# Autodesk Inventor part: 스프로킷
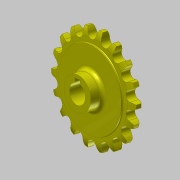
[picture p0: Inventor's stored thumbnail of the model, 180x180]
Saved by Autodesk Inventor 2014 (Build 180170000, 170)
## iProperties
Created: 2016-03
Part Number: 스프로킷
Material: 강철, 탄소
Document SubType Name: Modeling
Designer: mduedu
Density: 7.87 g/cm^3
Mass: 301.818 g
Surface Area: 124.882 cm^2
Volume: 38.3505 cm^3
Appearance: 매끄러움 - 노란색
Author: mduedu
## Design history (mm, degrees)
sketch "스케치1"
  geometry: L1 (0, 5)-(29.5, 5); L2 (29.5, 5)-(29.5, 4.1); L3 (30, 3.6)-(33.625, 3.6); L4 (40, 2)-(40, 0); L5 (40, 0)-(0, 0); L6 (0, 0)-(0, 5); L7 (0, -5)-(29.5, -5); L8 (29.5, -5)-(29.5, -4.1); L9 (30, -3.6)-(33.625, -3.6); L10 (40, -2)-(40, 0); L11 (0, 0)-(0, -5); A1 r 13.5 centre (33.625, -9.9) between (40, 2) and (33.625, 3.6); A2 r 13.5 centre (33.625, 9.9) between (33.625, -3.6) and (40, -2); A3 r 0.5 centre (30, 4.1) between (29.5, 4.1) and (30, 3.6); A4 r 0.5 centre (30, -4.1) between (30, -3.6) and (29.5, -4.1); 2 further points
  constraints: 22 end point, 8 point on circle, 6 symmetric about line, 5 tangent, 4 centre point, 4 parallel, 4 point on line, 1 equal radius, 1 horizontal, 1 perpendicular, 1 other
  dimensions: "d0" = 80 diameter of L4 L6; "d2" = 59 diameter of L2 L6; "d3" = 1.6 vertical distance of L4.start L3.end; "d4" = 3.6 distance from line of L4.end L3; "d5" = 5 distance between parallel lines of L5 L1; "d6" = 13.5 radius of A1; "d15" = 0.5 radius of A3
revolve "회전1" sketch "스케치1" stored, may be unused: angle "d7" = 90 deg
sketch "스케치2" dims "d8" = 65.2, "d11" = 80
  geometry: L1 (0, 0)-(0, 32.6); A1 r 36.57 centre (0, 0) between (-16.231, 32.771) and (0, 36.57); A2 r 3.97 centre (0, 36.57) between (-3.866, 35.665) and (0, 32.6); A3 r 12.7 centre (-16.231, 32.771) between (-3.866, 35.665) and (-5.534, 39.615); A4 r 12.7 centre (16.231, 32.771) between (5.534, 39.615) and (3.866, 35.665); A5 r 3.97 centre (0, 36.57) between (0, 32.6) and (3.866, 35.665); A6 r 40 centre (0, 0) between (5.534, 39.615) and (-5.534, 39.615); 2 further points
  constraints: 12 point on circle, 6 centre point, 4 coincident, 3 symmetric about line, 2 end point, 1 point on line, 1 tangent, 1 vertical, 1 vertical alignment, 7 other
  dimensions: "d10" = 73.14 diameter of A1; "d12" = 12.7 radius of A3
extrude "돌출1" cut sketch "스케치2" stored distance "d13" = 10; taper "d14" = 0 deg
sketch "스케치3"
  geometry: C1 r 12.5 at (0, 0); 1 further point
  constraints: 1 centre point, 1 coincident
  dimensions: "d19" = 25 diameter of C1
extrude "돌출2" join sketch "스케치3" distance "d20" = 10; taper "d21" = 0 deg
fillet "모깎기1" dims "d22" = 3
sketch "스케치4"
  geometry: L1 (-2.5, 0)-(2.5, 0); L2 (2.5, 0)-(2.5, 9.8); L3 (2.5, 9.8)-(-2.5, 9.8); L4 (-2.5, 9.8)-(-2.5, 0); C1 r 7.5 at (0, 0); 2 further points
  constraints: 8 end point, 2 coincident, 2 parallel, 1 centre point, 1 horizontal, 1 midpoint, 1 perpendicular
  dimensions: "d23" = 15 diameter of C1; "d25" = 5 distance of L2.end L3.end; "d26" = 9.8 distance of L1.end L2.end
extrude "돌출3" cut sketch "스케치4" stored distance "d27" = 8; taper "d28" = 0 deg
node "솔리드1"
pattern_circular "원형 패턴1" dims angle "d17" = 360 deg
